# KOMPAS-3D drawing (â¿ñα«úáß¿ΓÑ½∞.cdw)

Referenced files in C:\Documents and Settings\GooDMaN\Мои документы\Мои работы для шараги\Работы для помощников\Ремонт гидрогасителей\: Гидрогаситель.frw
Referenced files in C:\Documents and Settings\rwlib\Мои документы\Контент для сайта pomogala\Дипломные работы\Тема № 6 Гидравлические гасители колебаний\: Гидрогаситель.cdw
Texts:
  ВСТАВЬ СВОЙ ШИФР
  Гидравлический гаситель  колебаний
  GooDMaN
  Домашний пк
  Текст на чертеже
  Размерные надписи
  Шероховатость
  Линия-выноска #1
  Линия-выноска #2
  Линия-выноска #3
  Отклонения формы и база
  Заголовок таблицы
  Ячейка таблицы
  Стрелка вида
  Обозначение изменения
  Фигурная скобка
  Номер узла
  Марка координационной оси
  VRCB
  Выносная надпись
  Обозначение узла
  Марка/позиционное обозначение с линией-выноской
  Марка/позиционное обозначение на линии
  Марка/позиционное обозначение без линии-выноски
  Слой 1
  Гидравлический гаситель
  колебаний
  Иванов
  ПУ-1 гр. №1
  ПЭР.30.4.00.00.08.ВО-
Dimensions and other numbers on the sheet: 7; 1; 2; 3; 4; 5; 6; 0; 8; 9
